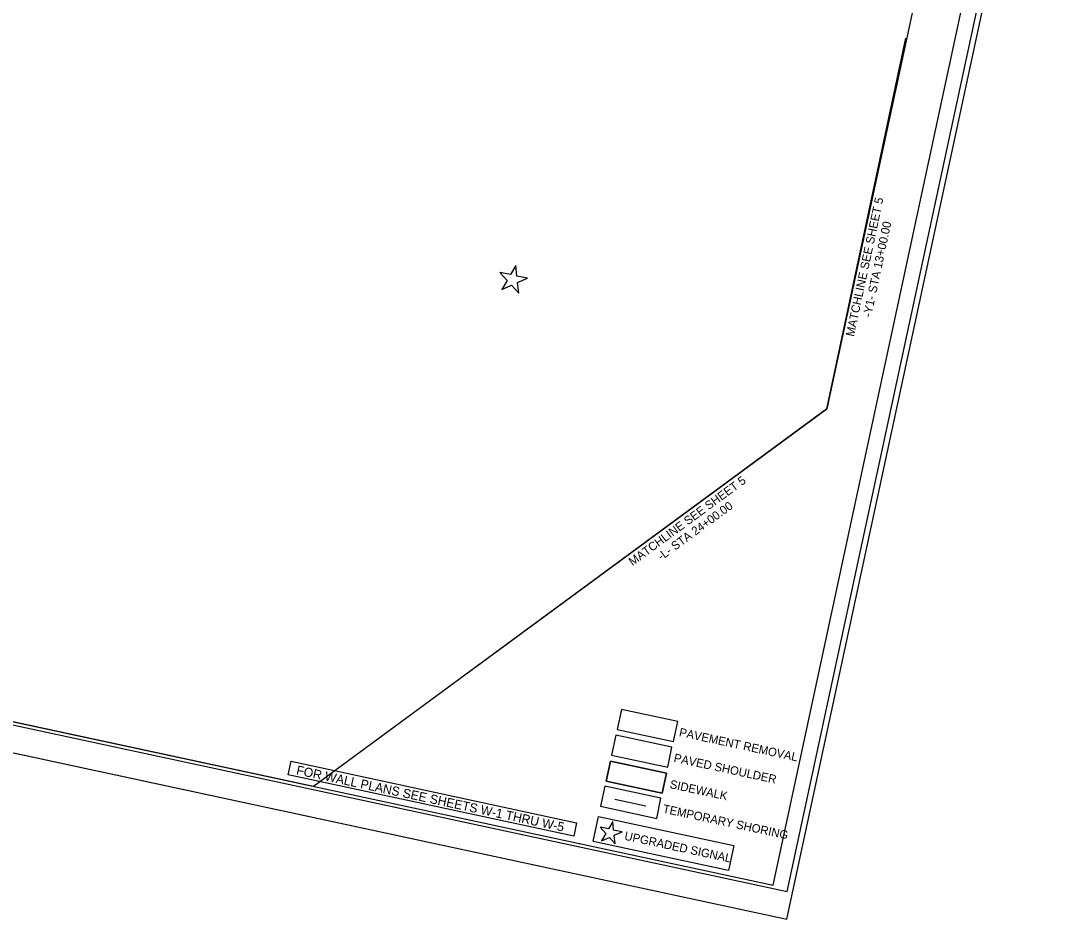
# Model space of a CAD drawing. Extents: x 1761851 to 1763953, y 711926 to 713410.
# Drawn here: x 1762902 to 1763765, y 711926 to 712668 of the extents above; entities that cross this region are included whole.
import ezdxf

# ---------------------------------------------------------------- set-up
doc = ezdxf.new("R2010")
doc.units = 0
for name, color, linetype in [('Matchline', 7, 'Continuous'), ('Matchline Text', 7, 'Continuous'), ('Old_Level_40', 7, 'Continuous'), ('Prop DSN Text', 7, 'Continuous'), ('Prop Grid Mask', 7, 'Continuous'), ('Prop Horizontal Alignment Station Label', 7, 'Continuous'), ('Prop RDY Traffic Signal CELL', 7, 'Continuous'), ('Prop Shade Light', 7, 'Continuous'), ('Prop Shade Medium', 7, 'Continuous'), ('Scratch_Level_3', 7, 'Continuous'), ('Sheet Border Standard 30in CELL', 7, 'Continuous'), ('Sheet Cutting Line CELL', 7, 'Continuous'), ('Sheet Plot Border Inside CELL', 7, 'Continuous'), ('Sheet Plot Border Outside CELL', 7, 'Continuous'), ('Temp Shoring', 7, 'Continuous')]:
    doc.layers.add(name, color=color, linetype=linetype)

msp = doc.modelspace()

# ---------------------------------------------------------------- linework, layer by layer
at = {"layer": 'Matchline'}
for p, q in [((1763567.05, 712347.56), (1763632.34, 712653.65)), ((1763269.11, 712128.5), (1763567.05, 712347.56))]:
    msp.add_line(p, q, dxfattribs=at)
at = {"layer": 'Old_Level_40'}
for points in [[(1763443.94, 712089.5), (1763397.68, 712099.45), (1763394.11, 712082.89), (1763440.38, 712072.94)], [(1763439.23, 712068.38), (1763392.97, 712078.33), (1763389.41, 712061.76), (1763435.67, 712051.81)], [(1763434.62, 712046.93), (1763388.36, 712056.88), (1763384.8, 712040.32), (1763431.06, 712030.37)], [(1763430.15, 712026.14), (1763383.89, 712036.09), (1763380.32, 712019.53), (1763426.59, 712009.58)]]:
    msp.add_lwpolyline(points, close=True, dxfattribs=at)
at = {"layer": 'Prop Grid Mask'}
for points in [[(1763124.88, 712056.66), (1763360.55, 712005.98), (1763358.16, 711994.84), (1763122.49, 712045.52)], [(1763378.53, 712011.19), (1763490.3, 711987.16), (1763485.85, 711966.49), (1763374.09, 711990.52)]]:
    msp.add_lwpolyline(points, close=True, dxfattribs=at)
at = {"layer": 'Prop RDY Traffic Signal CELL'}
for points in [[(1763305.89, 712458.47), (1763297.25, 712460.33), (1763303.15, 712453.75), (1763298.7, 712446.08), (1763306.81, 712449.67), (1763312.72, 712443.08), (1763311.81, 712451.88), (1763319.9, 712455.46), (1763311.25, 712457.32), (1763310.34, 712466.13), (1763305.89, 712458.47)], [(1763386.8, 712000.86), (1763379.89, 712002.34), (1763384.61, 711997.08), (1763381.05, 711990.95), (1763387.53, 711993.81), (1763392.26, 711988.54), (1763391.53, 711995.58), (1763398.01, 711998.45), (1763391.09, 711999.94), (1763390.36, 712006.99), (1763386.8, 712000.86)]]:
    msp.add_lwpolyline(points, dxfattribs=at)
at = {"layer": 'Prop Shade Light'}
msp.add_lwpolyline([(1763388.36, 712056.88), (1763434.62, 712046.93), (1763431.06, 712030.37), (1763384.8, 712040.32)], close=True, dxfattribs=at)
at = {"layer": 'Prop Shade Medium'}
msp.add_lwpolyline([(1763439.23, 712068.38), (1763392.97, 712078.33), (1763389.41, 712061.76), (1763435.67, 712051.81), (1763439.23, 712068.38)], dxfattribs=at)
at = {"layer": 'Scratch_Level_3'}
for p, q in [((1763648.59, 712726.73), (1763567.05, 712347.56)), ((1763567.05, 712347.56), (1763143.31, 712036)), ((1763143.31, 712036), (1762056.2, 712269.77))]:
    msp.add_line(p, q, dxfattribs=at)
at = {"layer": 'Sheet Border Standard 30in CELL'}
msp.add_lwpolyline([(1763743.42, 712980.95), (1762276.95, 713296.31), (1762056.2, 712269.77), (1763522.68, 711954.42)], close=True, dxfattribs=at)
at = {"layer": 'Sheet Cutting Line CELL'}
msp.add_line((1761887.68, 712280.44), (1763534.04, 711926.4), dxfattribs=at)
at = {"layer": 'Sheet Plot Border Inside CELL'}
msp.add_lwpolyline([(1763756.18, 712980.82), (1762126.92, 713331.17), (1761905.11, 712299.65), (1763534.36, 711949.3)], close=True, dxfattribs=at)
at = {"layer": 'Sheet Plot Border Outside CELL'}
msp.add_lwpolyline([(1763765.3, 713001.82), (1762118.93, 713355.86), (1761887.68, 712280.44), (1763534.04, 711926.4)], close=True, dxfattribs=at)
at = {"layer": 'Temp Shoring'}
msp.add_line((1763392.15, 712025.42), (1763417.55, 712019.96), dxfattribs=at)

# ---------------------------------------------------------------- texts
at = {"layer": 'Matchline Text'}
for s, rotation, p in [('MATCHLINE SEE SHEET 5 ', 77.9593, (1763589.42, 712406.92)), ('-Y1- STA 13+00.00', 77.9593, (1763603.57, 712422.93)), ('MATCHLINE SEE SHEET 5 ', 36.31424, (1763406.67, 712217.75)), ('-L- STA 24+00.00', 36.31424, (1763430.44, 712222.19))]:
    msp.add_text(s, height=7, rotation=rotation, dxfattribs=at).set_placement(p)
at = {"layer": 'Prop DSN Text'}
for s, p in [('PAVEMENT REMOVAL', (1763444.64, 712077.53)), ('PAVED SHOULDER', (1763440.24, 712056.34)), ('SIDEWALK', (1763436.93, 712034.61)), ('TEMPORARY SHORING', (1763431.17, 712014.36)), ('UPGRADED SIGNAL', (1763399.51, 711991.93))]:
    msp.add_text(s, height=7, rotation=347.86389, dxfattribs=at).set_placement(p)
at = {"layer": 'Prop Horizontal Alignment Station Label'}
msp.add_text('FOR WALL PLANS SEE SHEETS W-1 THRU W-5', height=7.5, rotation=347.86389, dxfattribs=at).set_placement((1763128.71, 712045.98))

doc.saveas('drawing.dxf')
